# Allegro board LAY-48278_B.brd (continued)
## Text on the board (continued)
User.20: TOP TO LAYER X | BACK DRILL REFERENCE | BOTTOM TO LAYER X | LAYER X | MUST CUT LAYER | LAYER X+1 | MUST NOT CUT LAYER | LAYER X-1
User.21: FIGURE | FINISHED_SIZE | 10.0 | 18.0 | 40.0 | 41.0 | 15.0 | 250.0 | DRILL CHART: TOP to BOTTOM | ALL UNITS ARE IN MILS | TOLERANCE_DRILL | +0.0/-10.0 | +0.0/-18.0 | +3.0/-3.0 | +2.0/-2.0 | PLATED | NON-PLATED | QTY | 250 | 58 | 31 | 14 | 11 | 2
